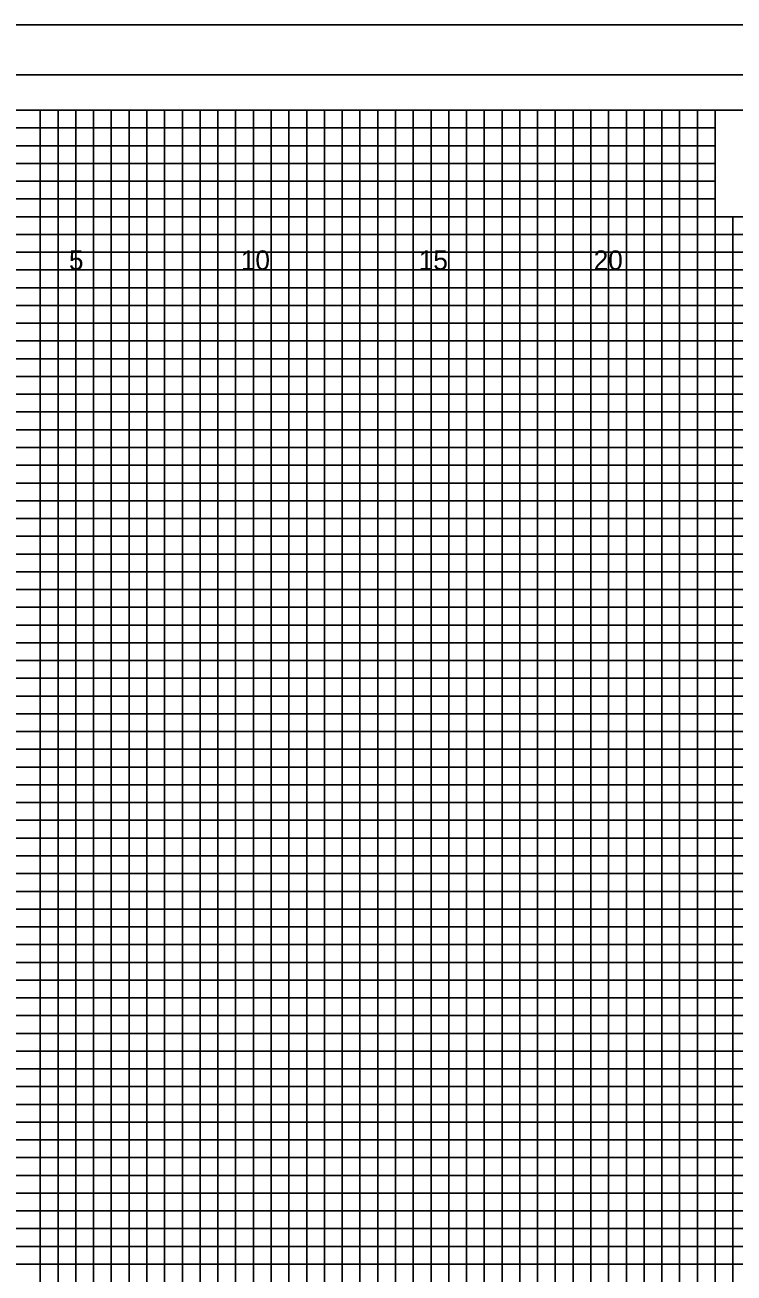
# Model space of a CAD drawing. Extents: x -4 to 103, y -2 to 209.
# Drawn here: x 54.82 to 74.78, y 32.25 to 67.4 of the extents above; entities that cross this region are included whole.
import ezdxf

# ---------------------------------------------------------------- set-up
doc = ezdxf.new("R2010")
doc.units = 0
for name, color, linetype in [('Old_Level_10', 7, 'Continuous'), ('Old_Level_16', 7, 'Continuous'), ('Old_Level_17', 7, 'Continuous'), ('Old_Level_3', 7, 'Continuous'), ('Old_Level_5', 7, 'Continuous'), ('Old_Level_6', 7, 'Continuous'), ('Old_Level_8', 7, 'Continuous'), ('Typical Curb CELL', 7, 'Continuous')]:
    doc.layers.add(name, color=color, linetype=linetype)

msp = doc.modelspace()

# ---------------------------------------------------------------- linework, layer by layer
at = {"layer": 'Old_Level_10'}
for p, q in [((56.25, 0), (56.25, 65)), ((58.75, 0), (58.75, 65)), ((61.25, 0), (61.25, 65)), ((63.75, 0), (63.75, 65)), ((66.25, 0), (66.25, 65)), ((68.75, 0), (68.75, 65)), ((71.25, 0), (71.25, 65)), ((73.75, 0), (73.75, 65)), ((0, 62.5), (74.25, 62.5)), ((0, 60), (102.5, 60)), ((0, 57.5), (102.5, 57.5)), ((0, 55), (102.5, 55)), ((0, 52.5), (102.5, 52.5)), ((0, 50), (102.5, 50)), ((0, 47.5), (102.5, 47.5)), ((0, 45), (102.5, 45)), ((0, 42.5), (102.5, 42.5)), ((0, 40), (102.5, 40)), ((0, 37.5), (102.5, 37.5)), ((0, 35), (102.5, 35)), ((0, 32.5), (102.5, 32.5))]:
    msp.add_line(p, q, dxfattribs=at)
at = {"layer": 'Old_Level_17'}
for points in [[(55.25, 0), (55.25, 65), (55.75, 65), (55.75, 0)], [(56.75, 0), (56.75, 65), (57.25, 65), (57.25, 0)], [(57.75, 0), (57.75, 65), (58.25, 65), (58.25, 0)], [(59.25, 0), (59.25, 65), (59.75, 65), (59.75, 0)], [(60.25, 0), (60.25, 65), (60.75, 65), (60.75, 0)], [(61.75, 0), (61.75, 65), (62.25, 65), (62.25, 0)], [(62.75, 0), (62.75, 65), (63.25, 65), (63.25, 0)], [(64.25, 0), (64.25, 65), (64.75, 65), (64.75, 0)], [(65.25, 0), (65.25, 65), (65.75, 65), (65.75, 0)], [(66.75, 0), (66.75, 65), (67.25, 65), (67.25, 0)], [(67.75, 0), (67.75, 65), (68.25, 65), (68.25, 0)], [(69.25, 0), (69.25, 65)], [(69.25, 65), (69.75, 65), (69.75, 0)], [(70.25, 0), (70.25, 65), (70.75, 65), (70.75, 0)], [(71.75, 0), (71.75, 65), (72.25, 65), (72.25, 0)], [(72.75, 0), (72.75, 65), (73.25, 65), (73.25, 0)], [(0, 62), (0, 63), (74.25, 63), (74.25, 63.5), (0, 63.5), (0, 64), (74.25, 64), (74.25, 64.5), (0, 64.5)], [(0, 61.5), (102.5, 61.5), (102.5, 62), (0, 62)], [(74.25, 0), (74.25, 62), (74.75, 62), (74.75, 0)], [(0, 60.5), (102.5, 60.5), (102.5, 61), (0, 61)], [(0, 59), (102.5, 59), (102.5, 59.5), (0, 59.5)], [(0, 58), (102.5, 58), (102.5, 58.5), (0, 58.5)], [(0, 56.5), (102.5, 56.5), (102.5, 57), (0, 57)], [(0, 55.5), (102.5, 55.5), (102.5, 56), (0, 56)], [(0, 54), (102.5, 54), (102.5, 54.5), (0, 54.5)], [(0, 53), (102.5, 53), (102.5, 53.5), (0, 53.5)], [(0, 51.5), (102.5, 51.5), (102.5, 52), (0, 52)], [(0, 50.5), (102.5, 50.5), (102.5, 51), (0, 51)], [(0, 49), (102.5, 49), (102.5, 49.5), (0, 49.5)], [(0, 48), (102.5, 48), (102.5, 48.5), (0, 48.5)], [(0, 46.5), (102.5, 46.5), (102.5, 47), (0, 47)], [(0, 45.5), (102.5, 45.5), (102.5, 46), (0, 46)], [(0, 44), (102.5, 44), (102.5, 44.5), (0, 44.5)], [(0, 43), (102.5, 43), (102.5, 43.5), (0, 43.5)], [(0, 41.5), (102.5, 41.5), (102.5, 42), (0, 42)], [(0, 40.5), (102.5, 40.5), (102.5, 41), (0, 41)], [(0, 39), (102.5, 39), (102.5, 39.5), (0, 39.5)], [(0, 38), (102.5, 38), (102.5, 38.5), (0, 38.5)], [(0, 36.5), (102.5, 36.5), (102.5, 37), (0, 37)], [(0, 35.5), (102.5, 35.5), (102.5, 36), (0, 36)], [(0, 34), (102.5, 34), (102.5, 34.5), (0, 34.5)], [(0, 33), (102.5, 33), (102.5, 33.5), (0, 33.5)]]:
    msp.add_lwpolyline(points, dxfattribs=at)
at = {"layer": 'Old_Level_3'}
msp.add_line((-3.5, 67.4), (103.4, 67.4), dxfattribs=at)
at = {"layer": 'Old_Level_5'}
msp.add_lwpolyline([(103.4, 67.4), (-3.5, 67.4), (-3.5, -2.425), (103.4, -2.425)], close=True, dxfattribs=at)
at = {"layer": 'Old_Level_6'}
for points in [[(102.5, 65), (0, 65), (0, 0), (102.5, 0)], [(83.75, 65), (74.25, 65), (74.25, 62), (83.75, 62)]]:
    msp.add_lwpolyline(points, close=True, dxfattribs=at)
at = {"layer": 'Old_Level_8'}
for points in [[(56.25, 0), (56.25, 65), (58.75, 65), (58.75, 0)], [(61.25, 0), (61.25, 65), (63.75, 65), (63.75, 0)], [(66.25, 0), (66.25, 65), (68.75, 65), (68.75, 0)], [(71.25, 0), (71.25, 65), (73.75, 65), (73.75, 0)], [(0, 62.5), (74.25, 62.5)], [(0, 57.5), (102.5, 57.5), (102.5, 60), (0, 60)], [(0, 52.5), (102.5, 52.5), (102.5, 55), (0, 55)], [(0, 47.5), (102.5, 47.5), (102.5, 50), (0, 50)], [(0, 42.5), (102.5, 42.5), (102.5, 45), (0, 45)], [(0, 37.5), (102.5, 37.5), (102.5, 40), (0, 40)], [(0, 32.5), (102.5, 32.5), (102.5, 35), (0, 35)]]:
    msp.add_lwpolyline(points, dxfattribs=at)
at = {"layer": 'Typical Curb CELL'}
msp.add_lwpolyline([(103, 66), (-2.8, 66), (-2.8, -1), (103, -1)], close=True, dxfattribs=at)

# ---------------------------------------------------------------- texts
at = {"layer": 'Old_Level_16'}
for s, p in [('5', (56.0574, 60.5)), ('10', (60.8971, 60.5)), ('15', (65.9057, 60.5)), ('20', (70.8312, 60.5))]:
    msp.add_text(s, height=0.55, dxfattribs=at).set_placement(p)

doc.saveas('drawing.dxf')
